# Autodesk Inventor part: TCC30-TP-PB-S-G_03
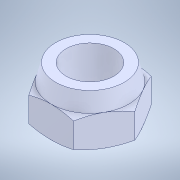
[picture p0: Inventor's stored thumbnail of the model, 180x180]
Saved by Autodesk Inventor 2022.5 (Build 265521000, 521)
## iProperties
Created: 2023-09
Part Number: TCC30-TP-PB-S-G_03
Material: 一般
Document SubType Name: Modeling
Designer: ImaoCorp
Density: 1 g/cm^3
Appearance: 既定
Author: ImaoCorp
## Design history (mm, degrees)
feature "TCC30-TP-PB-S-G_03"
node "ソリッド1"
